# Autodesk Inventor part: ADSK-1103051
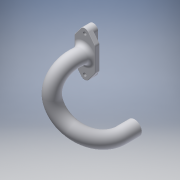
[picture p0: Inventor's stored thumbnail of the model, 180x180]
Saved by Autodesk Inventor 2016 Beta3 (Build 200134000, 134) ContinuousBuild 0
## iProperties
Shininess: 41.0
Length Units: 11272
Angle Units: 11279
Time Units: 11290
Mass Units: 11286
Length Display Precision: 4
Angle Display Precision: 2
Compacted: True
Created: 2000-08
Part Number: ADSK-1103051
Document SubType Name: Modeling
Mass: 3.87512 g
Surface Area: 71.1546 cm^2
Volume: 3.87512 cm^3
Density: 1 g/cm^3
Material: Generic
Appearance: Default
Density: 0.0
Volumn: 0.0
Area: 0.0
PropertySet Name: Model Information
Control State: 0
Master: False
Checked Out: False
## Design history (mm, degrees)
node "Extrusion1" dims "d0" = 3.175, "d1" = 0
  sketch "Sketch3"
    geometry: L1 (-24.5, -3.018)-(-24.5, 22.982) reference; L2 (-23, 0.482)-(-23, 18.482) reference; L3 (-22, 19.482)-(-20, 19.482) reference; L4 (-17.5, 22.982)-(-17.5, -3.018) reference; L5 (-19, 18.482)-(-19, 0.482) reference; L6 (-20, -0.518)-(-22, -0.518) reference; A1 r 3.5 centre (-21, 22.982) between (-17.5, 22.982) and (-24.5, 22.982) reference; A2 r 1 centre (-22, 18.482) between (-22, 19.482) and (-23, 18.482) reference; A3 r 1 centre (-20, 18.482) between (-19, 18.482) and (-20, 19.482) reference; A4 r 3.5 centre (-21, -3.018) between (-24.5, -3.018) and (-17.5, -3.018) reference; A5 r 1 centre (-22, 0.482) between (-23, 0.482) and (-22, -0.518) reference; A6 r 1 centre (-20, 0.482) between (-20, -0.518) and (-19, 0.482) reference
    constraints: 12 end point, 12 point on circle, 6 centre point, 4 vertical, 2 horizontal, 24 other
node "Extrusion2" dims "d4" = 3.175, "d5" = 0
  sketch "Sketch4"
    geometry: L1 (-19, 18.482)-(-19, 0.482) reference; L2 (-24.5, -3.018)-(-24.5, 22.982) reference; L3 (-17.5, 22.982)-(-17.5, -3.018) reference; L4 (-23.785, -5.139)-(-28.62, 1.211); L5 (-28.62, 1.211)-(-28.62, 18.752); L6 (-28.62, 18.752)-(-23.785, 25.102); L7 (-18.215, -5.139)-(-13.38, 1.211); L8 (-13.38, 1.211)-(-13.38, 18.752); L9 (-13.38, 18.752)-(-18.215, 25.102); A1 r 3.5 centre (-21, 22.982) between (-17.5, 22.982) and (-24.5, 22.982) reference; A2 r 3.5 centre (-21, -3.018) between (-24.5, -3.018) and (-17.5, -3.018) reference
    constraints: 12 end point, 4 parallel, 4 point on circle, 4 tangent, 2 equal length
    dimensions: "d2" = 15.24 distance between parallel lines of L8 L5; "d3" = 6.35 vertical distance of L4.start L4.end
node "Loft1" dims "d7" = 3.3, "d8" = 90 deg, "d9" = 3.3, "d10" = 90 deg
  sketch "Sketch5"
    geometry: L1 (22, 19.482)-(20, 19.482) reference; L2 (19, 18.482)-(19, 0.482) reference; L3 (20, -0.518)-(22, -0.518) reference; L4 (23, 0.482)-(23, 18.482) reference; A1 r 1 centre (20, 18.482) between (20, 19.482) and (19, 18.482) reference; A2 r 1 centre (20, 0.482) between (19, 0.482) and (20, -0.518) reference; A3 r 1 centre (22, 0.482) between (22, -0.518) and (23, 0.482) reference; A4 r 1 centre (22, 18.482) between (23, 18.482) and (22, 19.482) reference
  sketch "Sketch6"
    geometry: L1 (-28.62, 1.211)-(-28.62, 18.752) reference; L2 (-21, -3.018)-(-21, 22.982); C1 r 4.445 at (-21, 9.982); A1 r 3.5 centre (-21, 22.982) between (-18.215, 25.102) and (-23.785, 25.102) reference; A2 r 3.5 centre (-21, -3.018) between (-23.785, -5.139) and (-18.215, -5.139) reference
    constraints: 2 end point, 1 centre point, 1 midpoint, 1 parallel
    dimensions: "d6" = 8.89 diameter of C1
node "Revolution1" dims "d14" = 15 deg
  sketch "Sketch7"
    geometry: L1 (-28.62, 1.211)-(-28.62, 18.752) reference; L2 (-13.38, 18.752)-(-13.38, 1.211) reference; C1 r 5.274 at (-21, 9.982); A1 r 3.5 centre (-21, -3.018) between (-23.785, -5.139) and (-18.215, -5.139) reference; 9 further points
    constraints: 2 horizontal alignment, 2 vertical alignment, 1 centre point, 1 midpoint, 6 other
    dimensions: "d12" = 10.54862 diameter of C1
node "Revolution2" dims "d15" = 94 deg
  sketch "Sketch8"
    geometry: L1 (6.987, -17.795)-(-7.412, -17.795); C1 r 5.274 at (0, 0) reference; 8 further points
    constraints: 2 end point, 1 horizontal, 1 horizontal alignment, 1 vertical alignment, 6 other
node "Revolution3" dims "d16" = 60 deg
  sketch "Sketch9"
    geometry: L1 (19.108, -8.183)-(22.735, 4.959); C1 r 5.274 at (0, 0) reference; 8 further points
    constraints: 2 end point, 8 other
node "Revolution4" dims "d17" = 75 deg
  sketch "Sketch10"
    geometry: L1 (20.068, 21.365)-(23.424, -2.949); L2 (8.121, 19.463)-(55.018, 25.936) reference; C1 r 5.274 at (0, 0) reference; 8 further points
    constraints: 2 end point, 1 perpendicular, 8 other
    dimensions: "d21" = 22.8011 distance from line of C1.centre L1
node "Extrusion3" dims "d18" = 9.525, "d19" = 0
  sketch "Sketch11"
    geometry: C1 r 5.274 at (0, 0) reference; 8 further points
    constraints: 8 other
fillet "Fillet2" dims "d22" = 2.54
fillet "Fillet4" dims "d24" = 0.3175
fillet "Fillet5" dims "d25" = 3.175
workaxis "Work Axis1"
hole "Hole1" diameter "d28" = 2.45872; stored, may be unused: countersink angle "d32" = 82 deg, drill point angle "d34" = 118 deg; dims "d26" = 25.4, "d27" = 25.4, "d29" = 12.7, "d30" = 9.525, "d31" = 6.35, "d33" = 19.05
hole "Hole2" diameter "d37" = 2.45872; stored, may be unused: countersink angle "d41" = 82 deg, drill point angle "d43" = 118 deg; dims "d35" = 25.4, "d36" = 25.4, "d38" = 12.7, "d39" = 9.525, "d40" = 6.35, "d42" = 19.05
body "Solid1"
